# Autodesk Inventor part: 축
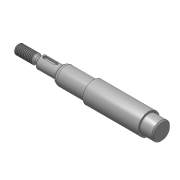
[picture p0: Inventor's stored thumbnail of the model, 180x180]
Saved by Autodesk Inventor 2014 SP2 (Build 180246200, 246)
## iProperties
Created: 2015-11
Part Number: 축
Material: 강철, 연강
Document SubType Name: Modeling
Designer: mduedu
Density: 1 g/cm^3
Appearance: 강철
Author: mduedu
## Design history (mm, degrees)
sketch "스케치1"
  geometry: L1 (-86, 0)-(86, 0); L2 (-86, 0)-(-86, 4); L3 (-86, 4)-(-70.732, 4); L4 (-70.732, 4)-(-69, 3); L5 (-69, 3)-(-67, 3); L6 (-67, 3)-(-67, 5); L7 (-67, 5)-(-49, 5); L8 (-49, 5)-(-49, 6.55); L9 (-47.355, 7.5)-(-23, 7.5); L10 (-23, 7.5)-(-23, 9); L11 (0, 0)-(0, 9); L12 (86, 4)-(70.732, 4); L13 (70.732, 4)-(69, 3); L14 (69, 3)-(67, 3); L15 (67, 3)-(67, 5); L16 (67, 5)-(49, 5); L17 (23, 7.5)-(23, 9); L18 (86, 0)-(86, 4); L19 (-23, 9)-(23, 9); L20 (-49, 6.55)-(-47.355, 7.5); L21 (47.355, 7.5)-(23, 7.5); L22 (49, 6.55)-(47.355, 7.5); L23 (49, 5)-(49, 6.55); 1 further point
  constraints: 46 end point, 10 symmetric about line, 6 perpendicular, 5 parallel, 2 midpoint, 1 coincident, 1 horizontal
  dimensions: "d0" = 172 distance of L1.start L1.end (derived); "d1" = 8 diameter of L3 L1; "d2" = 30 deg angle of L4 L5; "d3" = 6 diameter of L5 L1; "d4" = 10 diameter of L7 L1; "d5" = 15 diameter of L9 L1; "d6" = 18 diameter of L19 L1; "d8" = 18 distance of L6.end L7.end; "d9" = 46 distance of L10.end L17.end; "d10" = 2 distance of L4.end L5.end; "d11" = 17 distance from line of L4.end L2; "d16" = 13.1 diameter of L8.end L1; "d17" = 30 deg angle of L20 L9; "d18" = 26 distance between parallel lines of L10 L8
revolve "회전1" sketch "스케치1" stored, may be unused: angle "d12" = 90 deg
chamfer "모따기1" distance "d13" = 1; stored, may be unused: second distance "d14" = 2, angle "d15" = 45 deg
fillet "모깎기3" dims "d35" = 4
node "작업 평면1"
sketch "스케치2" dims "d23" = 12
  geometry: L1 (-5.5, 1.5)-(3.5, 1.5); L2 (3.5, 1.5)-(3.5, -1.5); L3 (3.5, -1.5)-(-5.5, -1.5); L4 (-5.5, -1.5)-(-5.5, 1.5); L5 (-9, -4)-(-9, 4) reference; 3 further points
  constraints: 8 end point, 2 midpoint, 2 parallel, 2 vertical alignment, 1 horizontal, 1 perpendicular, 4 other
  dimensions: "d21" = 3 distance between parallel lines of L3 L1; "d24" = 2 dimension on L5
extrude "돌출1" cut sketch "스케치2" distance "d25" = 1.8; taper "d26" = 0 deg
feature "스레드1" dims "d27" = 10, "d28" = 0
feature "스레드2" dims "d29" = 10, "d30" = 0
chamfer "모따기2" distance "d31" = 1; stored, may be unused: second distance "d32" = 2, angle "d33" = 45 deg
fillet "모깎기2" dims "d34" = 0.3
node "작업 평면2"
sketch "스케치3"
  geometry: C1 r 7.5 at (0, 0) reference; 1 further point
extrude "돌출2" cut sketch "스케치3" stored distance "d37" = 10; taper "d38" = 0 deg
chamfer "모따기3" distance "d39" = 1; stored, may be unused: second distance "d40" = 2, angle "d41" = 45 deg
node "솔리드1"
mirror "대칭1"
node "절단 모서리 투영1"
other parameters: "d36" = 11
